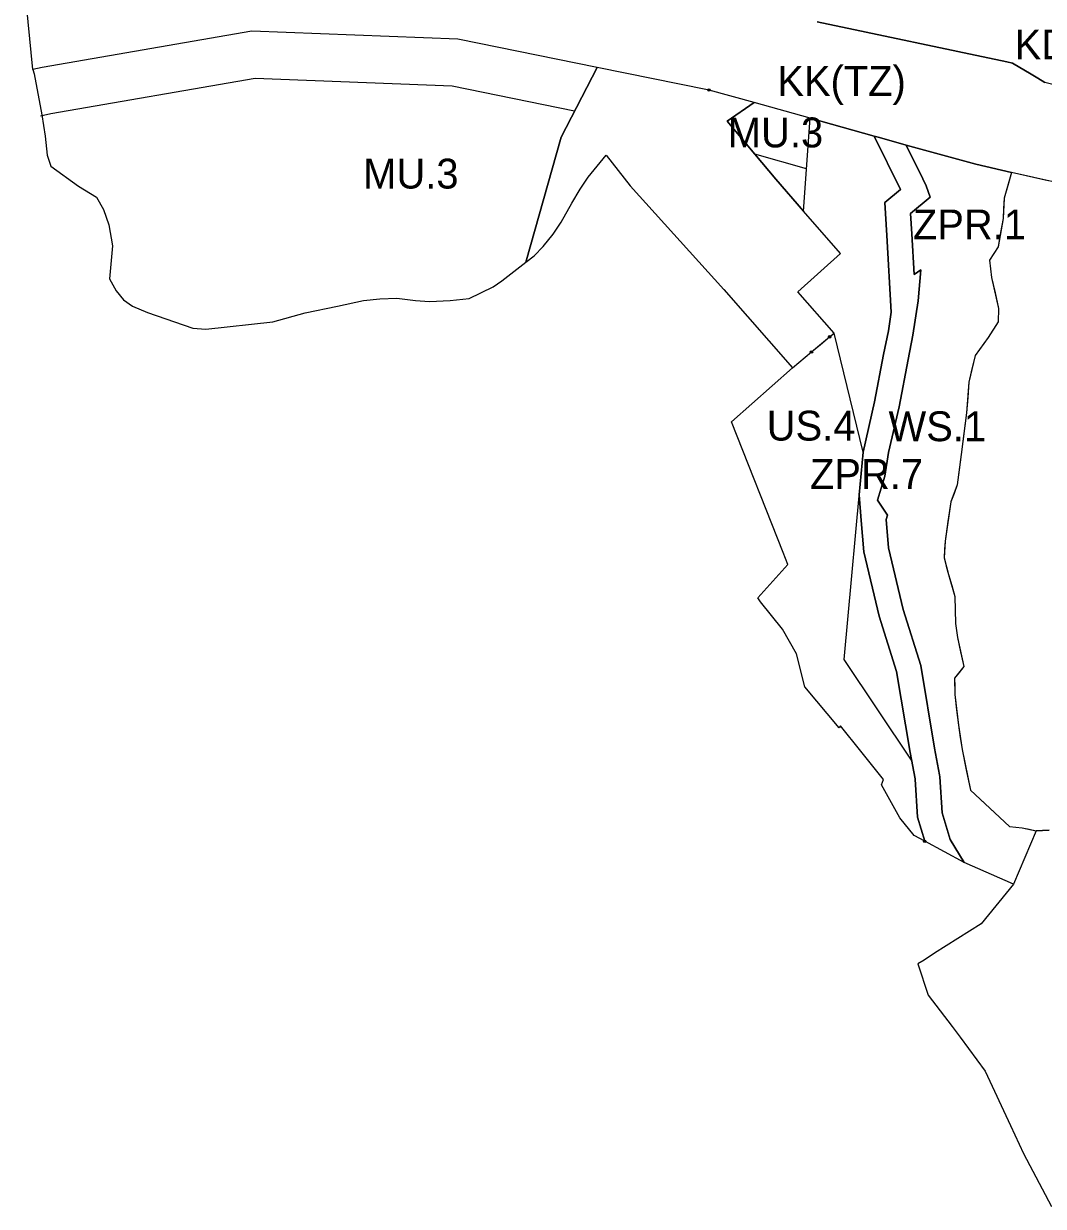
# Model space of a CAD drawing. Extents: x 7422965 to 7424741, y 5551047 to 5553849.
# Drawn here: x 7423618.8 to 7424028.7, y 5551463.8 to 5551939.4 of the extents above; entities that cross this region are included whole.
import ezdxf

# ---------------------------------------------------------------- set-up
doc = ezdxf.new("R2010")
doc.units = 0
for name, color, linetype in [('Default', 7, 'Continuous'), ('LIN_Linia Zabudowy Nieprzekraczalna', 7, 'Continuous'), ('linie_rozgraniczajace', 7, 'Continuous'), ('mpzp 340 REJON ULIC ŁOKIETKA - GLOGERA', 7, 'Continuous'), ('oznaczenia_przeznaczen', 7, 'Continuous'), ('Tereny dla których obowiązuje MPZP LInia tramwajowa_', 7, 'Continuous'), ('Tereny dla których obowiązuje MPZP_SIEWNA_', 7, 'Continuous')]:
    doc.layers.add(name, color=color, linetype=linetype)

msp = doc.modelspace()

# ---------------------------------------------------------------- linework, layer by layer
at = {"layer": 'Default'}
for centre in [(7423894.3, 5551912.66), (7423942.8, 5551813.42), (7423935.48, 5551807.34), (7423981.03, 5551610.6)]:
    msp.add_circle(centre, 0.5, dxfattribs=at)
at = {"layer": 'LIN_Linia Zabudowy Nieprzekraczalna'}
for points in [[(7423840.26, 5551904.22), (7423791.07, 5551914.24), (7423711.8, 5551917.3), (7423629.75, 5551903.06), (7423625.49, 5551902.19)], [(7423933.55, 5551881.04), (7423912.69, 5551886.89)], [(7423975.72, 5551643.23), (7423948.66, 5551683.65), (7423956.22, 5551767.03), (7423944.58, 5551814.87)]]:
    msp.add_lwpolyline(points, dxfattribs=at)
at = {"layer": 'linie_rozgraniczajace'}
for p, q in [((7423849.34, 5551921.76), (7423793.35, 5551933.17)), ((7423834.8, 5551893.66), (7423849.34, 5551921.76)), ((7423912.41, 5551907.63), (7423901.54, 5551900.08)), ((7423934.98, 5551901.31), (7423912.41, 5551907.63)), ((7423901.54, 5551900.08), (7423912.72, 5551886.85)), ((7423932.34, 5551863.96), (7423934.98, 5551901.31)), ((7423820.71, 5551843.5), (7423834.8, 5551893.66)), ((7423912.72, 5551886.85), (7423921.11, 5551876.87)), ((7423921.11, 5551876.87), (7423932.34, 5551863.96))]:
    msp.add_line(p, q, dxfattribs=at)
for points in [[(7424030.65, 5551876.21), (7424024.75, 5551877.53), (7424015.98, 5551879.5), (7424001.52, 5551882.86), (7423973.57, 5551890.53), (7423962.78, 5551893.52), (7423960.68, 5551894.11), (7423934.98, 5551901.31), (7423912.41, 5551907.63), (7423894.3, 5551912.66), (7423893.67, 5551912.79), (7423849.34, 5551921.76), (7423793.35, 5551933.17), (7423710.53, 5551936.36), (7423626.22, 5551921.73), (7423622.43, 5551920.96), (7423618.77, 5551959.44)], [(7424338.43, 5551944.9), (7424327.49, 5551937.52), (7424295.81, 5551916.92), (7424278.65, 5551903.92), (7424275.17, 5551900.11), (7424272.19, 5551895.33), (7424269.35, 5551890.42), (7424267.75, 5551885.84), (7424260.49, 5551865.76), (7424258.29, 5551856.52), (7424253.82, 5551857.89), (7424248.24, 5551859.6), (7424244.12, 5551860.87), (7424153.41, 5551884.24), (7424137.07, 5551888.39), (7424134.98, 5551888.92), (7424060.02, 5551907.95), (7424029.29, 5551915.75), (7424026.49, 5551917.43), (7424025.86, 5551917.8), (7424023.81, 5551919.03), (7424016.3, 5551923.51), (7424014.01, 5551923.99), (7423937.85, 5551940.09)], [(7423937.85, 5551940.09), (7424014.01, 5551923.99), (7424016.3, 5551923.51), (7424023.81, 5551919.03), (7424025.86, 5551917.8), (7424026.49, 5551917.43), (7424029.29, 5551915.75)], [(7423793.35, 5551933.17), (7423710.53, 5551936.36), (7423626.22, 5551921.73)], [(7423626.22, 5551921.73), (7423622.43, 5551920.96), (7423622.95, 5551919.19), (7423626.1, 5551902.73), (7423627.43, 5551894.15), (7423628.16, 5551886.54), (7423629.73, 5551882.03), (7423640.85, 5551874.03), (7423648.02, 5551869.59), (7423650.84, 5551864.69), (7423653.02, 5551858.47), (7423654.48, 5551849.96), (7423653.24, 5551836.78), (7423655.92, 5551831.99), (7423658.95, 5551828.31), (7423662.58, 5551825.76), (7423668.57, 5551823.16), (7423686.78, 5551816.91), (7423691.97, 5551816.55), (7423718.99, 5551819.5), (7423731.89, 5551823.03), (7423744.89, 5551825.76), (7423755.38, 5551828.04), (7423761.92, 5551828.69), (7423768.82, 5551828.95), (7423776.3, 5551828.05), (7423781.99, 5551827.7), (7423790.22, 5551828.04), (7423797.87, 5551828.85), (7423807.47, 5551833.57), (7423811.04, 5551835.99), (7423820.71, 5551843.5)]]:
    msp.add_lwpolyline(points, dxfattribs=at)
for points in [[(7423903.33, 5551779.29), (7423927.88, 5551800.97), (7423935.48, 5551807.34), (7423939.14, 5551810.38), (7423942.8, 5551813.42), (7423944.58, 5551814.87), (7423930.05, 5551831.58), (7423947.1, 5551846.99), (7423932.34, 5551863.96), (7423934.98, 5551901.31), (7423960.68, 5551894.11), (7423971.23, 5551872.62), (7423965.03, 5551867.43), (7423965.82, 5551854.21), (7423967.57, 5551823.32), (7423966.46, 5551815.82), (7423964.5, 5551806.31), (7423960.9, 5551787.32), (7423956.22, 5551767.03), (7423954.67, 5551749.94), (7423955.52, 5551739.51), (7423956.53, 5551726.97), (7423962.7, 5551701.14), (7423969.66, 5551678.91), (7423975.15, 5551646.29), (7423977.12, 5551635.74), (7423977.15, 5551635.51), (7423978.07, 5551620.24), (7423981.03, 5551610.61), (7423976.76, 5551612.89), (7423971.04, 5551620.07), (7423963.68, 5551633.24), (7423964.4, 5551635.48), (7423955.32, 5551646.79), (7423947.12, 5551657.01), (7423947.04, 5551656.86), (7423946.57, 5551656.27), (7423932.86, 5551672.75), (7423929.45, 5551685.9), (7423923.89, 5551695.86), (7423915.02, 5551706.81), (7423913.96, 5551708.54), (7423926.02, 5551721.9), (7423924.13, 5551726.71)], [(7423954.67, 5551749.94), (7423956.22, 5551767.03), (7423960.9, 5551787.32), (7423964.5, 5551806.31), (7423966.46, 5551815.82), (7423967.57, 5551823.32), (7423965.82, 5551854.21), (7423965.03, 5551867.43), (7423971.23, 5551872.62), (7423960.68, 5551894.11), (7423962.78, 5551893.52), (7423973.57, 5551890.53), (7423980.25, 5551876.93), (7423981.65, 5551874.1), (7423983.18, 5551869.59), (7423975.31, 5551863), (7423975.8, 5551854.79), (7423976.72, 5551838.54), (7423979.46, 5551840.43), (7423978.35, 5551827.93), (7423976.31, 5551814.07), (7423974.31, 5551804.36), (7423970.69, 5551785.28), (7423966.53, 5551766.91), (7423965, 5551757.43), (7423962.07, 5551747.73), (7423966.01, 5551741.76), (7423965.51, 5551739.95), (7423966.43, 5551728.55), (7423972.34, 5551703.8), (7423979.4, 5551681.25), (7423984.99, 5551648.04), (7423987, 5551637.33), (7423987.11, 5551636.47), (7423987.98, 5551622.04), (7423991.28, 5551611.31), (7423996.94, 5551602.1), (7423981.03, 5551610.61), (7423978.07, 5551620.24), (7423977.15, 5551635.51), (7423977.12, 5551635.74), (7423975.15, 5551646.29), (7423969.66, 5551678.91), (7423962.7, 5551701.14), (7423956.53, 5551726.97), (7423955.52, 5551739.51)], [(7423962.07, 5551747.73), (7423965, 5551757.43), (7423966.53, 5551766.91), (7423970.69, 5551785.28), (7423974.31, 5551804.36), (7423976.31, 5551814.07), (7423978.35, 5551827.93), (7423979.46, 5551840.43), (7423976.72, 5551838.54), (7423975.8, 5551854.79), (7423975.31, 5551863), (7423983.18, 5551869.59), (7423981.65, 5551874.1), (7423980.25, 5551876.93), (7423973.57, 5551890.53), (7424001.52, 5551882.86), (7424015.98, 5551879.5), (7424012.95, 5551869.12), (7424012.53, 5551861.02), (7424010.54, 5551849.67), (7424007.01, 5551844.27), (7424007.86, 5551837.3), (7424010.71, 5551824.83), (7424010.59, 5551819.43), (7424006.49, 5551813.12), (7424001.26, 5551805.92), (7423998.8, 5551795.22), (7423997.79, 5551782.86), (7423995.65, 5551766.16), (7423994.11, 5551753.85), (7423991.5, 5551747.1), (7423989.23, 5551731.21), (7423988.83, 5551724.6), (7423990.56, 5551717.82), (7423993.19, 5551708.98), (7423993.41, 5551698.21), (7423994.16, 5551692.58), (7423996.72, 5551680.82), (7423993.05, 5551676.18), (7423993.14, 5551669.6), (7423994.57, 5551657.24), (7423996.03, 5551647.43), (7423999.45, 5551631.19), (7424015.07, 5551616.59), (7424020.18, 5551616.04), (7424025.78, 5551614.83), (7424016.66, 5551593.3), (7423996.94, 5551602.1), (7423991.28, 5551611.31), (7423987.98, 5551622.04), (7423987.11, 5551636.47), (7423987, 5551637.33), (7423984.99, 5551648.04), (7423979.4, 5551681.25), (7423972.34, 5551703.8), (7423966.43, 5551728.55), (7423965.51, 5551739.95), (7423966.01, 5551741.76)]]:
    msp.add_lwpolyline(points, close=True, dxfattribs=at)
at = {"layer": 'mpzp 340 REJON ULIC ŁOKIETKA - GLOGERA'}
for p, q in [((7423901.54, 5551900.08), (7423912.41, 5551907.63)), ((7423820.71, 5551843.5), (7423824, 5551846.06)), ((7423935.48, 5551807.34), (7423942.8, 5551813.42)), ((7423942.8, 5551813.42), (7423944.58, 5551814.87)), ((7423927.88, 5551800.97), (7423935.48, 5551807.34))]:
    msp.add_line(p, q, dxfattribs=at)
for points in [[(7423893.67, 5551912.79), (7423849.34, 5551921.76), (7423834.8, 5551893.66), (7423820.71, 5551843.5)], [(7423912.41, 5551907.63), (7423894.3, 5551912.66), (7423893.67, 5551912.79)], [(7423921.11, 5551876.87), (7423912.72, 5551886.85), (7423901.54, 5551900.08)], [(7423824, 5551846.06), (7423827.61, 5551849.7), (7423831.71, 5551854.71), (7423834.86, 5551859.51), (7423839.22, 5551867.14), (7423842.45, 5551872.74), (7423845.69, 5551877.59), (7423852.89, 5551886.42), (7423862.57, 5551874.09), (7423900.25, 5551832.48), (7423927.88, 5551800.97)], [(7423947.1, 5551846.99), (7423932.34, 5551863.96), (7423921.11, 5551876.87)], [(7423944.58, 5551814.87), (7423930.05, 5551831.58), (7423947.1, 5551846.99)]]:
    msp.add_lwpolyline(points, dxfattribs=at)
at = {"layer": 'Tereny dla których obowiązuje MPZP LInia tramwajowa_'}
for points in [[(7424025.78, 5551614.83), (7424016.66, 5551593.3), (7424003.73, 5551577.42), (7423985, 5551565.61), (7423980.75, 5551562.77), (7423978.29, 5551561.28), (7423982.37, 5551548.78), (7423992, 5551536.13), (7423995.23, 5551531.88), (7424005.38, 5551518.1), (7424015.52, 5551496.35), (7424020.78, 5551485.05), (7424032.02, 5551463.8)], [(7424030.99, 5551615.11), (7424028.39, 5551614.97), (7424025.78, 5551614.83)]]:
    msp.add_lwpolyline(points, dxfattribs=at)
at = {"layer": 'Tereny dla których obowiązuje MPZP_SIEWNA_'}
msp.add_lwpolyline([(7424034.51, 5551875.34), (7424024.94, 5551877.49), (7424015.98, 5551879.5), (7424014.47, 5551874.31), (7424012.95, 5551869.12), (7424012.74, 5551865.07), (7424012.53, 5551861.02), (7424011.54, 5551855.35), (7424010.54, 5551849.67), (7424008.78, 5551846.97), (7424007.01, 5551844.27), (7424007.44, 5551840.79), (7424007.86, 5551837.3), (7424009.29, 5551831.07), (7424010.71, 5551824.83), (7424010.59, 5551819.43), (7424006.49, 5551813.12), (7424001.26, 5551805.92), (7424000.03, 5551800.57), (7423998.8, 5551795.22), (7423998.3, 5551789.04), (7423997.79, 5551782.86), (7423996.72, 5551774.51), (7423995.65, 5551766.16), (7423994.88, 5551760.01), (7423994.11, 5551753.85), (7423992.81, 5551750.48), (7423991.5, 5551747.1), (7423990.37, 5551739.15), (7423989.23, 5551731.21), (7423989.03, 5551727.9), (7423988.83, 5551724.6), (7423989.7, 5551721.21), (7423990.56, 5551717.82), (7423991.88, 5551713.4), (7423993.19, 5551708.98), (7423993.3, 5551703.6), (7423993.41, 5551698.21), (7423993.79, 5551695.4), (7423994.16, 5551692.58), (7423995.44, 5551686.7), (7423996.72, 5551680.82), (7423994.89, 5551678.5), (7423993.05, 5551676.18), (7423993.1, 5551672.89), (7423993.14, 5551669.6), (7423993.86, 5551663.42), (7423994.57, 5551657.24), (7423995.3, 5551652.34), (7423996.03, 5551647.43), (7423997.74, 5551639.31), (7423999.45, 5551631.19), (7424007.26, 5551623.89), (7424015.07, 5551616.59), (7424017.63, 5551616.32), (7424020.18, 5551616.04), (7424022.98, 5551615.44), (7424025.78, 5551614.83), (7424028.39, 5551614.97), (7424030.99, 5551615.11)], dxfattribs=at)

# ---------------------------------------------------------------- texts
at = {"layer": 'oznaczenia_przeznaczen'}
for s, p in [('KDZ', (7424017.2, 5551924.99)), ('KK(TZ)', (7423921.75, 5551910.32)), ('MU.3', (7423901.86, 5551889.61)), ('MU.3', (7423755.27, 5551873.06)), ('ZPR.1', (7423976.28, 5551852.61)), ('US.4', (7423917.51, 5551771.71)), ('WS.1', (7423966.48, 5551771.47)), ('ZPR.7', (7423934.89, 5551752.3))]:
    msp.add_text(s, height=12, dxfattribs=at).set_placement(p)

doc.saveas('drawing.dxf')
